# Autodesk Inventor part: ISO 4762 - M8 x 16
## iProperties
Comments: To add or edit properties for Autodesk Inventor files, use iProperties.
Created: 2004-07
Part Number: ISO 4762 - M8 x 16
Vendor: Autodesk Inc.
Document SubType Name: Modeling
Designer: John Blackburn
Material: Default
Description: Hexagon Socket Head Cap Screw
Standard: ISO 4762
Alert: To add or edit properties for Autodesk Inventor files, use iProperties.
Control State: 0
Master: False
Checked Out: False
Shininess: 64.0
Length Units: 11269
Angle Units: 11279
Time Units: 11290
Mass Units: 11283
Length Display Precision: 3
Angle Display Precision: 2
Compacted: True
EGR: 1
Density: 0.0
Volumn: 0.0
Area: 0.0
PropertySet Name: Model Information
Author: John Blackburn
Revision Number: 8
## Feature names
1. Body [Revolution]
2. Slot [Extrusion]
3. Fillet1
4. Chamfer1
